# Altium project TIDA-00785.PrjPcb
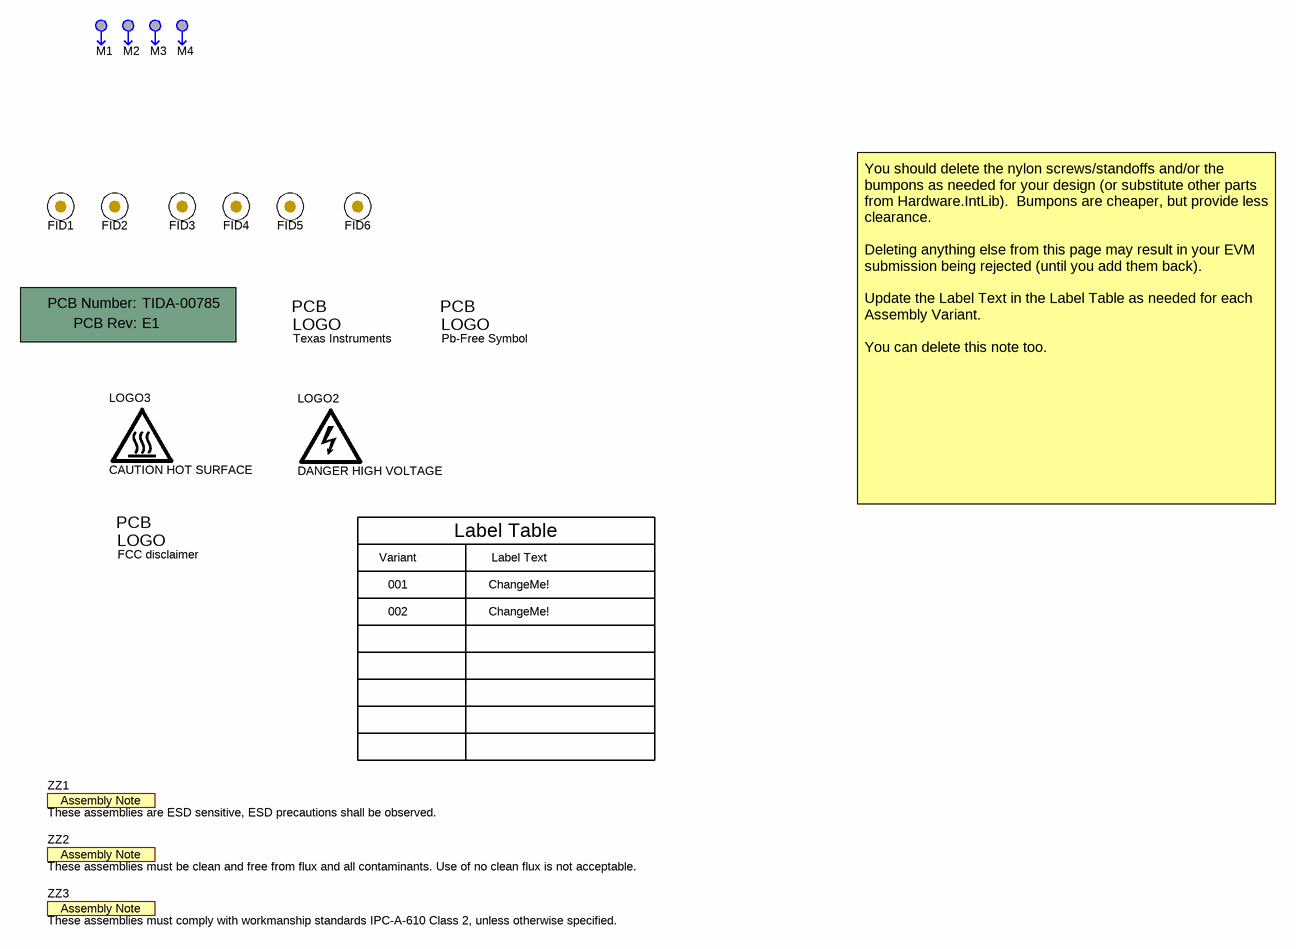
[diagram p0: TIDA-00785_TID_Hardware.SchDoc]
CopyrightYear: 2015; EVM_Orderable: N/A; PCB_Layout: BALAMURALI HS; PCB_Rev: E1; PRJ_Customer: Public Release; PRJ_Engineer: Neeraj Bhardwaj; PRJ_Number: TIDA-00785; PRJ_Title: ISO-GaN-Driver; SCH_Rev: E1; TechSupport: http://www.ti.com/support; TID: TIDA-00785
2 sheets, 53 parts. Net scope: global (net labels, ports and power ports of the same name join across sheets).
Board file: TIDA-00785_TID.PcbDoc
Sheets:
  TIDA-00785_TID_Hardware.SchDoc
  TIDA-00785_RefD-ISO-GaN-Driver.SchDoc

## Sheet TIDA-00785_TID_Hardware.SchDoc
size 431 x 279 mm; Date: Not shown in title block; ApprovedBy: Not shown in title block; CheckedBy: Not shown in title block; Author: Not shown in title block; CompanyName: Not shown in title block; Engineer: Not shown in title block; Organization: Not shown in title block; Address1: Not shown in title block; Address2: Not shown in title block; Address3: Not shown in title block; Address4: Not shown in title block; DocumentNumber: 1; Revision: Use project parameter SCH_Rev; SheetNumber: 3; SheetTotal: 3; PageSetup: Record=PageOptions¦CenterHorizontal=True¦CenterVertical=True¦PrintScale=1.00¦XCorrection=1.00¦YCorrection=1.00¦PrintKind=0¦BorderSize=5000000¦LeftOffset=0¦BottomOffset=0¦Orientation=2¦PaperLength=1000¦PaperWidth=1000¦Scale=100¦PaperSource=15¦PrintQuality=600¦MediaType=1¦DitherType=10¦PaperKind=Letter¦PrintScaleMode=1

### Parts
!PCB1  Printed Circuit Board  (value not drawn)  (mechanical)
FID1  Fiducial  [Fiducial10-20]  (value not drawn)
FID2  Fiducial  [Fiducial10-20]  (value not drawn)
FID3  Fiducial  [Fiducial10-20]  (value not drawn)
FID4  Fiducial  [Fiducial10-20]  (value not drawn)
FID5  Fiducial  [Fiducial10-20]  (value not drawn)
FID6  Fiducial  [Fiducial10-20]  (value not drawn)
Logo1  Texas Instruments  [TI_Stacked_Overlay_Small]  (no BOM)
LOGO2  DANGER HIGH VOLTAGE  [IEC_HighVoltage_small]  (no BOM)
LOGO3  CAUTION HOT SURFACE  [IEC_HotSurface_small]  (no BOM)
Logo4  Pb-Free Symbol  [Pb-Free_Overlay_Small]  (no BOM)
Logo5  FCC disclaimer  [FCC_disclaimer]  (no BOM)
M1  Suggest using a net name here  [Keystone_11073]  (value not drawn)
M2  Suggest using a net name here  [Keystone_11073]  (value not drawn)
M3  Suggest using a net name here  [Keystone_11073]  (value not drawn)
M4  Suggest using a net name here  [Keystone_11073]  (value not drawn)
ZZ1  These assemblies are ESD sensitive, ESD precautions shall be observed.  [AssemblyNote]  (no BOM)
ZZ2  These assemblies must be clean and free from flux and all contaminants. Use of no clean flux is not acceptable.  [AssemblyNote]  (no BOM)
ZZ3  These assemblies must comply with workmanship standards IPC-A-610 Class 2, unless otherwise specified.  [AssemblyNote]  (no BOM)

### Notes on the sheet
- Variant
- Label Table
- Label Text
- You should delete the nylon screws/standoffs and/or the bumpons as needed for your design (or substitute other parts from Hardware.IntLib).  Bumpons are cheaper, but provide less clearance.
  Deleting anything else from this page may result in your EVM submission being rejected (until you add them back).
  Update the Label Text in the Label Table as needed for each Assembly Variant.
  You can delete this note too.
- 001
- 002
- ChangeMe!

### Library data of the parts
!PCB1 = PCB: Manufacturer: Any; PartNumber: TIDA-00785; SymbolCreator: a0412235
FID1-FID6 = Fiducial: Fiducial mark.  There is nothing to buy or mount.; SymbolCreator: codlsc
Logo1 = TI_Logo: Texas Instrument Corporate Signature; SymbolCreator: codlsc
LOGO2 = IEC_HighVoltage: IEC 61010-1 High Voltage Warning; SymbolCreator: a0412235
LOGO3 = IEC_HotSurface: IEC 61010-1 Hot Surface Warning; SymbolCreator: a0412235
Logo4 = Pb-Free: SymbolCreator: a0412235
Logo5 = FCC_disclaimer: SymbolCreator: codlsc
M1-M4 = 11073: CONN PC PIN CIRC 0.040DIA TIN; Manufacturer: Keystone; CompType: PCB Pin
ZZ1-ZZ3 = AssemblyNote: SymbolCreator: codlsc

## Sheet TIDA-00785_RefD-ISO-GaN-Driver.SchDoc: RefD-ISO-GaN-Driver
size 431 x 279 mm; VersionControl_RevNumber: E1; Date: Not shown in title block; ApprovedBy: Not shown in title block; CheckedBy: Not shown in title block; Author: Not shown in title block; CompanyName: Not shown in title block; DrawnBy: Neeraj Bhardwaj; Engineer: Not shown in title block; Organization: Not shown in title block; Address1: Not shown in title block; Address2: Not shown in title block; Address3: Not shown in title block; Address4: Not shown in title block; DocumentNumber: 1; Revision: Use project parameter SCH_Rev; SheetNumber: 2; SheetTotal: 3; PageSetup: Record=PageOptions¦CenterHorizontal=True¦CenterVertical=True¦PrintScale=1.00¦XCorrection=1.00¦YCorrection=1.00¦PrintKind=0¦BorderSize=5000000¦LeftOffset=0¦BottomOffset=0¦Orientation=2¦PaperLength=1000¦PaperWidth=1000¦Scale=100¦PaperSource=15¦PrintQuality=600¦MediaType=1¦DitherType=10¦PaperKind=Letter¦PrintScaleMode=1
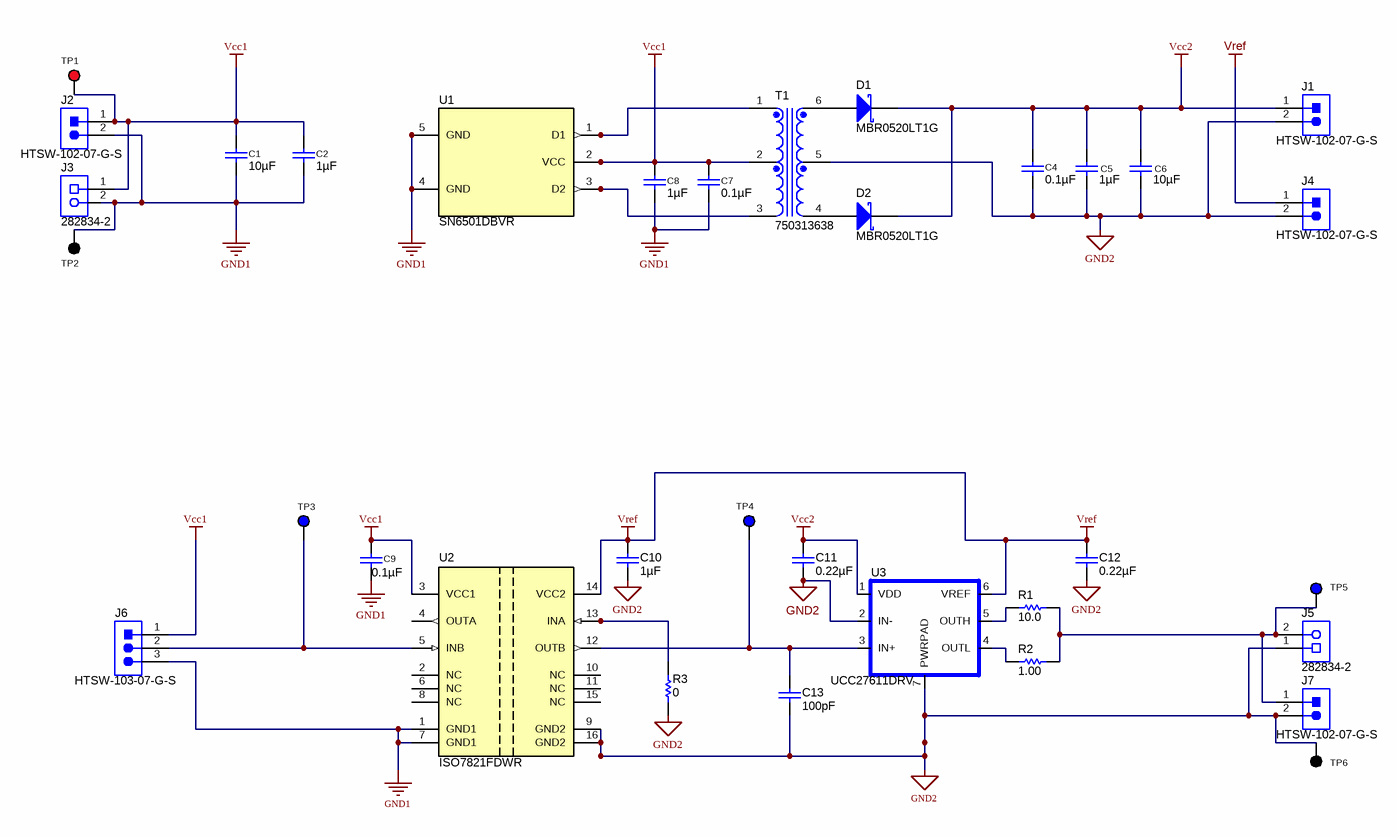
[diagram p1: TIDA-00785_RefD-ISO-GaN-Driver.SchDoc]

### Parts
C1  ValueDisplayed: 10µF  [0805_HV]  (hidden comment: GRM21BR6YA106KE43L)
C2  ValueDisplayed: 1µF  [0603]  (hidden comment: GRM188R61H105KAALD)
C4  ValueDisplayed: 0.1µF  [0603]  (hidden comment: 06033C104JAT2A)
C5  ValueDisplayed: 1µF  [0603]  (hidden comment: GRM188R61H105KAALD)
C6  ValueDisplayed: 10µF  [0805_HV]  (hidden comment: GRM21BR6YA106KE43L)
C7  ValueDisplayed: 0.1µF  [0603]  (hidden comment: 06033C104JAT2A)
C8  ValueDisplayed: 1µF  [0603]  (hidden comment: GRM188R61H105KAALD)
C9  ValueDisplayed: 0.1µF  [0603]  (hidden comment: 06033C104JAT2A)
C10  ValueDisplayed: 1µF  [0603]  (hidden comment: GRM188R61E105KA12D)
C11  ValueDisplayed: 0.22µF  [0402]  (hidden comment: C1005X7R1C224K050BC)
C12  ValueDisplayed: 0.22µF  [0402]  (hidden comment: C1005X7R1C224K050BC)
C13  ValueDisplayed: 100pF  [0402]  (hidden comment: C0402C101J3GACTU)
D1  MBR0520LT1G  [SOD-123]
D2  MBR0520LT1G  [SOD-123]
J1  HTSW-102-07-G-S  [Samtec_HTSW-102-07-G-S]
J2  HTSW-102-07-G-S  [Samtec_HTSW-102-07-G-S]
J3  282834-2  [TEC_282834-2]
J4  HTSW-102-07-G-S  [Samtec_HTSW-102-07-G-S]
J5  282834-2  [TEC_282834-2]
J6  HTSW-103-07-G-S  [Samtec_HTSW-103-07-G-S]
J7  HTSW-102-07-G-S  [Samtec_HTSW-102-07-G-S]
R1  ValueDisplayed: 10.0  [0805_HV]  (hidden comment: CRCW080510R0FKEA)
R2  ValueDisplayed: 1.00  [0805_HV]  (hidden comment: CRCW08051R00FKEA)
R3  ValueDisplayed: 0  [0603]  (hidden comment: CRCW06030000Z0EA)
T1  750313638  [Wurth_750313638]
TP1  5005  [Keystone5005]  (value not drawn)
TP2  5006  [Keystone5006]  (value not drawn)
TP3  5122  [Keystone5122]  (value not drawn)
TP4  5122  [Keystone5122]  (value not drawn)
TP5  5122  [Keystone5122]  (value not drawn)
TP6  5006  [Keystone5006]  (value not drawn)
U1  SN6501DBVR  [DBV0005A_N]
U2  ISO7821FDWR  [DW0016B_N]
U3  UCC27611DRV  [DRV]

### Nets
GND1: C1.2 C2.2 C7.2 C8.2 C9.2 J2.2 J3.2 J6.3 TP2.1 U1.4(GND) U1.5(GND) U2.1(GND1) U2.7(GND1)
GND2: C4.2 C5.2 C6.2 C10.2 C11.2 C12.2 C13.2 J1.2 J4.2 J5.1 J7.2 R3.1 T1.5 TP6.1 U2.9(GND2) U2.16(GND2) U3.2(IN-) U3.7(PWRPAD)
Vcc1: C1.1 C2.1 C7.1 C8.1 C9.1 J2.1 J3.1 J6.1 T1.2 TP1.1 U1.2(VCC) U2.3(VCC1)
Vcc2: C4.1 C5.1 C6.1 C11.1 D1.1(K) D2.1(K) J1.1 U3.1(VDD)
Vref: C10.1 C12.1 J4.1 U2.14(VCC2) U3.6(VREF)
NetC13_1: C13.1 TP4.1 U2.12(OUTB) U3.3(IN+)
NetD1_2: D1.2(A) T1.6
NetD2_2: D2.2(A) T1.4
NetJ5_2: J5.2 J7.1 R1.2 R2.2 TP5.1
NetJ6_2: J6.2 TP3.1 U2.5(INB)
NetR1_1: R1.1 U3.5(OUTH)
NetR2_1: R2.1 U3.4(OUTL)
NetR3_2: R3.2 U2.13(INA)
NetT1_1: T1.1 U1.1(D1)
NetT1_3: T1.3 U1.3(D2)

Not connected (* = marked no-connect by the designer): U2 2(NC) 4(OUTA) 6(NC) 8(NC) 10(NC) 11(NC) 15(NC)

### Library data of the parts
C1 C6 = GRM21BR6YA106KE43L: CAP, CERM, 10 µF, 35 V, +/- 10%, X5R, 0805; Manufacturer: MuRata; Polarized: N; CompType: Capacitor; Value: 10uF; U/M: EA; Cap_F: 0.00001; Tolerance_%: 10; Value1: Unknown; VDC_V: 35; Value2: 35V; TaMin_C: -55; TaMax_C: 85; Cap_Case: 0805
C2 C5 C8 = GRM188R61H105KAALD: CAP, CERM, 1 µF, 50 V, +/- 10%, X5R, 0603; Manufacturer: MuRata; Polarized: N; CompType: Capacitor; Value: 1uF; U/M: EA; Cap_F: 0.000001; Tolerance_%: 10; Value1: Unknown; VDC_V: 50; Value2: 50V; TaMin_C: -55; TaMax_C: 85
C4 C7 C9 = 06033C104JAT2A: CAP, CERM, 0.1 µF, 25 V, +/- 5%, X7R, 0603; Manufacturer: AVX; Polarized: N; CompType: Capacitor; Value: 0.1uF; U/M: EA; Cap_F: 0.0000001; Tolerance_%: 5; ESR_ohm: 0.05; Value1: 0.05 ohm; VDC_V: 25; Value2: 25V; TaMin_C: -55; TaMax_C: 125
C10 = GRM188R61E105KA12D: CAP, CERM, 1 µF, 25 V, +/- 10%, X5R, 0603; Manufacturer: MuRata; Polarized: N; CompType: Capacitor; Value: 1uF; U/M: EA; Cap_F: 0.000001; Tolerance_%: 10; Value1: Unknown; VDC_V: 25; Value2: 25V; TaMin_C: -55; TaMax_C: 85; AEC Category: Q200
C11 C12 = C1005X7R1C224K050BC: CAP, CERM, 0.22 µF, 16 V, +/- 10%, X7R, 0402; Manufacturer: TDK; Polarized: N; CompType: Capacitor; Value: 0.22uF; U/M: EA; Cap_F: 0.00000022; Tolerance_%: 10; Value1: Unknown; VDC_V: 16; Value2: 16V; TaMin_C: -55; TaMax_C: 125; AEC Category: Q200
C13 = C0402C101J3GACTU: CAP, CERM, 100 pF, 25 V, +/- 5%, C0G/NP0, 0402; Manufacturer: Kemet; Polarized: N; CompType: Capacitor; Value: 100pF; U/M: EA; Cap_F: 0.0000000001; Tolerance_%: 5; Value1: Unknown; VDC_V: 25; Value2: 25V; TaMin_C: -55; TaMax_C: 125; AEC Category: Q200
D1 D2 = MBR0520LT1G: Diode, Schottky, 20 V, 0.5 A, SOD-123; Manufacturer: ON Semiconductor; U/M: EA; Vf_V: 0.385; Value: 20V; Value1: 0.5A; Value2: 0.385V; Io_A: 0.5; Vr_V: 20; TJmax_C: 125; RJC_CperW: 150; AEC Category: Q101
J1 J2 J4 J7 = HTSW-102-07-G-S: Header, 100mil, 2x1, Gold, TH; Manufacturer: Samtec; SymbolCreator: a0412235; U/M: EA
J3 J5 = 282834-2: Terminal Block, 2x1, 2.54mm, TH; Manufacturer: TE Connectivity; SymbolCreator: a0412235; U/M: EA
J6 = HTSW-103-07-G-S: Header, 100mil, 3x1, Gold, TH; Manufacturer: Samtec; SymbolCreator: a0799628; U/M: EA
R1 = CRCW080510R0FKEA: RES, 10.0, 1%, 0.125 W, 0805; Manufacturer: Vishay-Dale; CompType: Resistor; Value: 10.0; Res_ohm: 10; Value_Code: 10R0; Tolerance_%: 1; Power_W: 0.125; Value2: 0.125W; VDC_V: 150; TempCo: 100 ppm/C; EIA_Code: E96; U/M: EA; AEC Category: Q200
R2 = CRCW08051R00FKEA: RES, 1.00, 1%, 0.125 W, 0805; Manufacturer: Vishay-Dale; CompType: Resistor; Value: 1.00; Res_ohm: 1; Value_Code: 1R00; Power_W: 0.125; Value2: 0.125W; VDC_V: 150; TempCo: 100 ppm/C; EIA_Code: E96; U/M: EA; AEC Category: Q200
R3 = CRCW06030000Z0EA: RES, 0, 5%, 0.1 W, 0603; Manufacturer: Vishay-Dale; CompType: Resistor; Value: 0; Value_Code: 0000; Tolerance_%: 5; Power_W: 0.1; Value2: 0.1W; VDC_V: 75; TempCo: 200 ppm/C; EIA_Code: E24; U/M: EA
T1 = 750313638: Transformer, 340 uH, SMT; Manufacturer: Wurth Elektronik; SymbolCreator: Altium; DCR_Ohm: 0.33; Value: 340uH; U/M: EA
TP1 = 5005: Test Point, Compact, Red, TH; Manufacturer: Keystone; CompType: Test Point Loop; U/M: EA
TP2 TP6 = 5006: Test Point, Compact, Black, TH; Manufacturer: Keystone; CompType: Test Point Loop; U/M: EA
TP3-TP5 = 5122: Test Point, Compact, Blue, TH; Manufacturer: Keystone; CompType: Test Point Loop; U/M: EA
U1 = SN6501DBVR: Transformer Driver for Isolated Power Supplies, DBV0005A; Alternate PartNumber: SN6501DBVT; Manufacturer: Texas Instruments; SymbolCreator: a0411947; CompType: IC; U/M: EA
U2 = ISO7821FDWR: High-Performance, 8000 VPK Reinforced Dual Channel Digital Isolator, DW0016B; Manufacturer: Texas Instruments; SymbolCreator: Altium; CompType: IC; U/M: EA
U3 = UCC27611DRV: IC, 4A/8A Single Channel High-Speed Low-Side Gate Drivers; Manufacturer: TI; Alternate Manufacturer: None; Area: 23360

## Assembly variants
001: not fitted FID1 FID2 FID3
